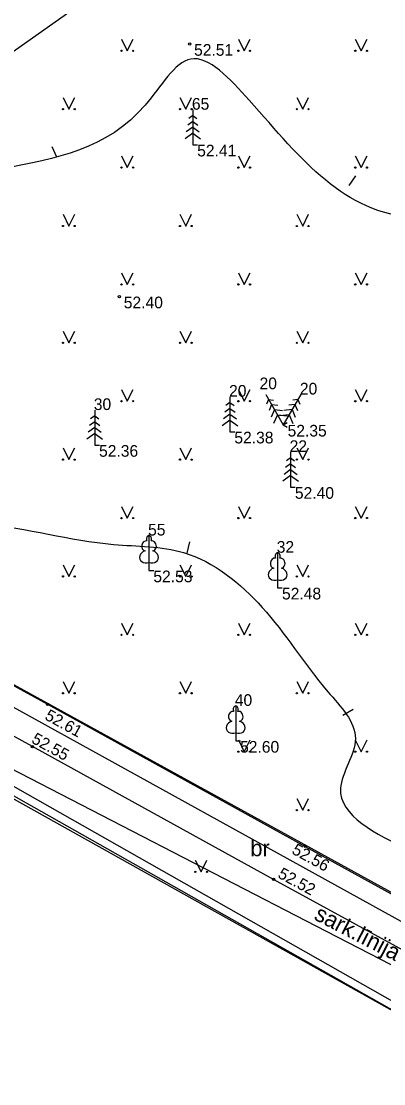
# Model space of a CAD drawing. Extents: x 619806 to 620082, y 405176 to 405386.
# Drawn here: x 619952.97 to 619968.46, y 405203.29 to 405248.76 of the extents above; entities that cross this region are included whole.
import ezdxf

# ---------------------------------------------------------------- set-up
doc = ezdxf.new("R2010")
doc.units = 0
for name, color, linetype in [('APGR_SARK_####_####_#', 7, 'Continuous'), ('APGR_SARK_IZNL_TKST_#', 7, 'Continuous'), ('APGS_VADP_ZSPR_####_#', 7, 'Continuous'), ('CELI_CMAL_####_####_#', 7, 'Continuous'), ('CELI_CSEG_####_TKST_#', 7, 'Continuous'), ('RAMI_UZMR_####_####_#', 7, 'Continuous'), ('RELJ_AATZ_####_TKST_#', 7, 'Continuous'), ('RELJ_ELEM_####_####_#', 7, 'Continuous'), ('RELJ_HORZ_PAMT_####_#', 7, 'Continuous'), ('ROBZ_UZMR_####_####_#', 7, 'Continuous'), ('SAKK_KKAN_####_####_#', 7, 'Continuous'), ('SAKT_VADP_KABE_####_#', 7, 'Continuous'), ('TERT_DIAM_####_TKST_#', 7, 'Continuous'), ('TERT_ELEM_####_####_#', 7, 'Continuous')]:
    doc.layers.add(name, color=color, linetype=linetype)

msp = doc.modelspace()

# ---------------------------------------------------------------- linework, layer by layer
at = {"layer": 'APGR_SARK_####_####_#'}
msp.add_lwpolyline([(619990.053, 405197.403), (619966.019, 405209.806), (619941.986, 405222.21), (619880.273, 405256.839), (619818.56, 405291.467)], dxfattribs=at)
at = {"layer": 'APGS_VADP_ZSPR_####_#'}
msp.add_lwpolyline([(619827.279, 405290.766), (619828.233, 405290.484), (619831.689, 405284.666), (619835.137, 405280.637), (619844.802, 405275.519), (619857.367, 405269.037), (619864.044, 405264.897), (619871.373, 405258.791), (619881.17, 405253.384), (619884.232, 405252.778), (619898.622, 405244.594), (619910.805, 405239.254), (619917.273, 405236.249), (619923.426, 405231.863), (619936.8, 405224.512), (619938.618, 405223.547), (619972.929, 405204.127)], dxfattribs=at)
at = {"layer": 'CELI_CMAL_####_####_#'}
for points in [[(619982.283, 405204.018), (619982.381, 405205.526), (619981.404, 405213.543), (619980.879, 405217.395), (619980.193, 405224.262), (619979.707, 405227.554), (619978.646, 405227.479), (619978.06, 405232.469), (619979.052, 405232.579), (619978.008, 405242.924), (619976.591, 405255.672), (619975.781, 405263.512), (619969.844, 405259.482), (619963.066, 405254.752), (619955.624, 405249.587), (619947.422, 405243.791), (619942.081, 405239.98), (619941.835, 405240.299), (619936.133, 405229.455), (619943.441, 405225.387), (619954.092, 405219.528), (619965.106, 405213.442), (619974.994, 405207.99), (619982.283, 405204.018)], [(619978.752, 405201.011), (619979.424, 405202.021), (619979.564, 405202.436), (619979.607, 405202.714), (619979.55, 405203.052), (619979.303, 405203.399), (619978.982, 405203.652), (619974.243, 405206.289), (619963.757, 405212.03), (619953.443, 405217.716), (619942.194, 405223.883), (619933.774, 405228.562), (619924.371, 405233.711), (619924.04, 405233.797), (619923.689, 405233.804), (619923.346, 405233.679), (619923.051, 405233.473), (619922.837, 405233.256), (619922.669, 405233.014)]]:
    msp.add_lwpolyline(points, dxfattribs=at)
at = {"layer": 'RAMI_UZMR_####_####_#'}
msp.add_lwpolyline([(619874.687, 405324.979), (619926.719, 405349.544), (619966.669, 405369.042), (620021.738, 405292.03), (620049.703, 405275.476), (620026.189, 405242.287), (620012.147, 405222.917), (619996.603, 405200.928), (619989.997, 405199.173), (619982.328, 405199.155), (619922.669, 405233.014), (619882.137, 405255.756), (619859.084, 405268.056), (619820.646, 405290.715), (619813.744, 405295.206), (619820.645, 405298.752)], close=True, dxfattribs=at)
at = {"layer": 'RELJ_ELEM_####_####_#'}
for centre in [(619960.169, 405247.788), (619957.163, 405236.978), (619954.092, 405219.528), (619953.443, 405217.716), (619965.106, 405213.442), (619963.757, 405212.03)]:
    msp.add_circle(centre, 0.05, dxfattribs=at)
at = {"layer": 'RELJ_HORZ_PAMT_####_#'}
for p, q in [((619954.489, 405242.94), (619954.285, 405243.396)), ((619966.986, 405241.735), (619967.276, 405242.143)), ((619960.16, 405226.477), (619960.046, 405225.991)), ((619967.156, 405219.304), (619966.723, 405219.054))]:
    msp.add_line(p, q, dxfattribs=at)
msp.add_spline([(619952.192, 405242.46), (619958.269, 405245.178), (619960.212, 405247.147), (619962.71, 405245.388), (619969.834, 405240.326), (619973.191, 405239.787), (619973.537, 405236.062), (619972.621, 405231.011), (619971.007, 405227.497), (619970.308, 405225.195), (619972.877, 405224.18), (619975.834, 405223.443), (619975.125, 405220.25), (619977.669, 405218.792), (619978.775, 405216.928), (619978.459, 405213.841), (619976.501, 405213.003), (619972.992, 405212.359), (619969.535, 405213.328), (619966.616, 405215.931), (619967.251, 405218.057), (619966.078, 405220.067), (619963.269, 405223.678), (619959.906, 405226.02), (619956.916, 405226.372), (619951.315, 405227.272), (619948.301, 405227.78), (619946.134, 405229.326), (619943.292, 405232.49), (619942.821, 405234.331), (619944.296, 405235.783), (619946.209, 405238.021), (619948.046, 405239.888), (619950.691, 405241.967), (619952.192, 405242.46)], degree=3, dxfattribs=at)
at = {"layer": 'ROBZ_UZMR_####_####_#'}
msp.add_line((619982.318, 405204.025), (619936.15, 405229.445), dxfattribs=at)
at = {"layer": 'SAKK_KKAN_####_####_#'}
msp.add_line((619979.31, 405204.647), (619918.714, 405238.138), dxfattribs=at)
at = {"layer": 'SAKT_VADP_KABE_####_#'}
msp.add_lwpolyline([(619817.668, 405301.762), (619818.308, 405291.251), (619820.058, 405288.244), (619821.78, 405286.435), (619865.996, 405262.382), (619894.538, 405246.913), (619928.954, 405228.717), (619988.18, 405195.595)], dxfattribs=at)
at = {"layer": 'TERT_ELEM_####_####_#'}
for p, q in [((619957.25, 405248), (619957.5, 405247.5)), ((619957.5, 405247.5), (619957.75, 405248)), ((619962.25, 405248), (619962.5, 405247.5)), ((619962.5, 405247.5), (619962.75, 405248)), ((619967.25, 405248), (619967.5, 405247.5)), ((619967.5, 405247.5), (619967.75, 405248)), ((619954.75, 405245.5), (619955, 405245)), ((619955, 405245), (619955.25, 405245.5)), ((619959.75, 405245.5), (619960, 405245)), ((619960, 405245), (619960.25, 405245.5)), ((619964.75, 405245.5), (619965, 405245)), ((619965, 405245), (619965.25, 405245.5)), ((619960.301, 405244.728), (619960.125, 405244.6)), ((619960.301, 405244.978), (619960.301, 405243.478)), ((619960.301, 405244.728), (619960.475, 405244.6)), ((619960.301, 405244.228), (619960.023, 405244.024)), ((619960.301, 405244.478), (619960.085, 405244.32)), ((619960.301, 405244.478), (619960.517, 405244.32)), ((619960.301, 405244.228), (619960.579, 405244.024)), ((619960.301, 405243.978), (619959.969, 405243.734)), ((619960.301, 405243.978), (619960.635, 405243.734)), ((619960.301, 405243.478), (619960.501, 405243.478)), ((619957.25, 405243), (619957.5, 405242.5)), ((619957.5, 405242.5), (619957.75, 405243)), ((619962.25, 405243), (619962.5, 405242.5)), ((619962.5, 405242.5), (619962.75, 405243)), ((619967.25, 405243), (619967.5, 405242.5)), ((619967.5, 405242.5), (619967.75, 405243)), ((619954.75, 405240.5), (619955, 405240)), ((619955, 405240), (619955.25, 405240.5)), ((619959.75, 405240.5), (619960, 405240)), ((619960, 405240), (619960.25, 405240.5)), ((619964.75, 405240.5), (619965, 405240)), ((619965, 405240), (619965.25, 405240.5)), ((619957.25, 405238), (619957.5, 405237.5)), ((619957.5, 405237.5), (619957.75, 405238)), ((619962.25, 405238), (619962.5, 405237.5)), ((619962.5, 405237.5), (619962.75, 405238)), ((619967.25, 405238), (619967.5, 405237.5)), ((619967.5, 405237.5), (619967.75, 405238)), ((619954.75, 405235.5), (619955, 405235)), ((619955, 405235), (619955.25, 405235.5)), ((619959.75, 405235.5), (619960, 405235)), ((619960, 405235), (619960.25, 405235.5)), ((619964.75, 405235.5), (619965, 405235)), ((619965, 405235), (619965.25, 405235.5)), ((619957.25, 405233), (619957.5, 405232.5)), ((619957.5, 405232.5), (619957.75, 405233)), ((619962.25, 405233), (619962.5, 405232.5)), ((619962.5, 405232.5), (619962.75, 405233)), ((619963.418, 405232.788), (619964.168, 405231.489)), ((619964.918, 405232.788), (619964.168, 405231.489)), ((619967.25, 405233), (619967.5, 405232.5)), ((619967.5, 405232.5), (619967.75, 405233)), ((619961.891, 405232.444), (619961.715, 405232.316)), ((619961.891, 405232.694), (619961.891, 405231.194)), ((619961.891, 405232.444), (619962.065, 405232.316)), ((619963.543, 405232.572), (619963.455, 405232.373)), ((619963.543, 405232.572), (619963.758, 405232.548)), ((619963.668, 405232.355), (619963.56, 405232.11)), ((619963.668, 405232.355), (619963.934, 405232.326)), ((619964.668, 405232.355), (619964.402, 405232.326)), ((619964.793, 405232.572), (619964.577, 405232.549)), ((619964.668, 405232.355), (619964.776, 405232.11)), ((619964.793, 405232.572), (619964.88, 405232.374)), ((619956.106, 405231.874), (619955.93, 405231.746)), ((619956.106, 405232.124), (619956.106, 405230.624)), ((619956.106, 405231.874), (619956.28, 405231.746)), ((619961.891, 405231.944), (619961.613, 405231.74)), ((619961.891, 405232.194), (619961.675, 405232.036)), ((619961.891, 405232.194), (619962.107, 405232.036)), ((619961.891, 405231.944), (619962.169, 405231.74)), ((619963.793, 405232.139), (619963.654, 405231.823)), ((619963.918, 405231.922), (619963.752, 405231.545)), ((619963.793, 405232.139), (619964.136, 405232.101)), ((619963.918, 405231.922), (619964.329, 405231.878)), ((619964.418, 405231.922), (619964.008, 405231.877)), ((619964.543, 405232.139), (619964.2, 405232.101)), ((619964.418, 405231.922), (619964.585, 405231.544)), ((619964.543, 405232.139), (619964.682, 405231.823)), ((619956.106, 405231.374), (619955.828, 405231.17)), ((619956.106, 405231.624), (619955.89, 405231.466)), ((619956.106, 405231.624), (619956.322, 405231.466)), ((619956.106, 405231.374), (619956.384, 405231.17)), ((619961.891, 405231.694), (619961.559, 405231.45)), ((619961.891, 405231.694), (619962.225, 405231.45)), ((619964.168, 405231.489), (619964.341, 405231.589)), ((619964.168, 405231.489), (619964.341, 405231.389)), ((619956.106, 405231.124), (619955.774, 405230.88)), ((619956.106, 405231.124), (619956.44, 405230.88)), ((619961.891, 405231.194), (619962.091, 405231.194)), ((619954.75, 405230.5), (619955, 405230)), ((619955, 405230), (619955.25, 405230.5)), ((619956.106, 405230.624), (619956.306, 405230.624)), ((619959.75, 405230.5), (619960, 405230)), ((619960, 405230), (619960.25, 405230.5)), ((619964.75, 405230.5), (619965, 405230)), ((619965, 405230), (619965.25, 405230.5)), ((619964.48, 405230.075), (619964.304, 405229.947)), ((619964.48, 405230.325), (619964.48, 405228.825)), ((619964.48, 405230.075), (619964.654, 405229.947)), ((619964.48, 405229.575), (619964.202, 405229.371)), ((619964.48, 405229.825), (619964.264, 405229.667)), ((619964.48, 405229.825), (619964.696, 405229.667)), ((619964.48, 405229.575), (619964.758, 405229.371)), ((619964.48, 405229.325), (619964.148, 405229.081)), ((619964.48, 405229.325), (619964.814, 405229.081)), ((619964.48, 405228.825), (619964.68, 405228.825)), ((619957.25, 405228), (619957.5, 405227.5)), ((619957.5, 405227.5), (619957.75, 405228)), ((619962.25, 405228), (619962.5, 405227.5)), ((619962.5, 405227.5), (619962.75, 405228)), ((619967.25, 405228), (619967.5, 405227.5)), ((619967.5, 405227.5), (619967.75, 405228)), ((619954.75, 405225.5), (619955, 405225)), ((619955, 405225), (619955.25, 405225.5)), ((619958.427, 405225.599), (619958.427, 405225.252)), ((619959.75, 405225.5), (619960, 405225)), ((619960, 405225), (619960.25, 405225.5)), ((619964.75, 405225.5), (619965, 405225)), ((619965, 405225), (619965.25, 405225.5)), ((619958.427, 405225.252), (619958.627, 405225.252)), ((619963.929, 405224.862), (619963.929, 405224.515)), ((619963.929, 405224.515), (619964.129, 405224.515)), ((619957.25, 405223), (619957.5, 405222.5)), ((619957.5, 405222.5), (619957.75, 405223)), ((619962.25, 405223), (619962.5, 405222.5)), ((619962.5, 405222.5), (619962.75, 405223)), ((619967.25, 405223), (619967.5, 405222.5)), ((619967.5, 405222.5), (619967.75, 405223)), ((619954.75, 405220.5), (619955, 405220)), ((619955, 405220), (619955.25, 405220.5)), ((619959.75, 405220.5), (619960, 405220)), ((619960, 405220), (619960.25, 405220.5)), ((619964.75, 405220.5), (619965, 405220)), ((619965, 405220), (619965.25, 405220.5)), ((619962.136, 405218.305), (619962.136, 405217.958)), ((619962.136, 405217.958), (619962.336, 405217.958)), ((619962.25, 405218), (619962.5, 405217.5)), ((619962.5, 405217.5), (619962.75, 405218)), ((619967.25, 405218), (619967.5, 405217.5)), ((619967.5, 405217.5), (619967.75, 405218)), ((619964.75, 405215.5), (619965, 405215)), ((619965, 405215), (619965.25, 405215.5)), ((619960.404, 405212.856), (619960.654, 405212.356)), ((619960.654, 405212.356), (619960.904, 405212.856))]:
    msp.add_line(p, q, dxfattribs=at)
for points in [[(619958.427, 405226.752), (619958.427, 405225.599)], [(619958.517, 405226.52), (619958.516, 405226.521)], [(619963.929, 405226.015), (619963.929, 405224.862)], [(619964.019, 405225.783), (619964.018, 405225.784)], [(619962.136, 405219.458), (619962.136, 405218.305)], [(619962.226, 405219.226), (619962.225, 405219.227)]]:
    msp.add_lwpolyline(points, dxfattribs=at)
for centre, radius in [((619957.25, 405247.5), 0.028), ((619957.75, 405247.5), 0.0263), ((619962.25, 405247.5), 0.028), ((619962.75, 405247.5), 0.0263), ((619967.25, 405247.5), 0.028), ((619967.75, 405247.5), 0.0263), ((619954.75, 405245), 0.028), ((619955.25, 405245), 0.0263), ((619959.75, 405245), 0.028), ((619960.25, 405245), 0.0263), ((619964.75, 405245), 0.028), ((619965.25, 405245), 0.0263), ((619957.25, 405242.5), 0.028), ((619957.75, 405242.5), 0.0263), ((619962.25, 405242.5), 0.028), ((619962.75, 405242.5), 0.0263), ((619967.25, 405242.5), 0.028), ((619967.75, 405242.5), 0.0263), ((619954.75, 405240), 0.028), ((619955.25, 405240), 0.0263), ((619959.75, 405240), 0.028), ((619960.25, 405240), 0.0263), ((619964.75, 405240), 0.028), ((619965.25, 405240), 0.0263), ((619957.25, 405237.5), 0.028), ((619957.75, 405237.5), 0.0263), ((619962.25, 405237.5), 0.028), ((619962.75, 405237.5), 0.0263), ((619967.25, 405237.5), 0.028), ((619967.75, 405237.5), 0.0263), ((619954.75, 405235), 0.028), ((619955.25, 405235), 0.0263), ((619959.75, 405235), 0.028), ((619960.25, 405235), 0.0263), ((619964.75, 405235), 0.028), ((619965.25, 405235), 0.0263), ((619957.25, 405232.5), 0.028), ((619957.75, 405232.5), 0.0263), ((619962.25, 405232.5), 0.028), ((619962.75, 405232.5), 0.0263), ((619967.25, 405232.5), 0.028), ((619967.75, 405232.5), 0.0263), ((619954.75, 405230), 0.028), ((619955.25, 405230), 0.0263), ((619959.75, 405230), 0.028), ((619960.25, 405230), 0.0263), ((619964.75, 405230), 0.028), ((619965.25, 405230), 0.0263), ((619957.25, 405227.5), 0.028), ((619957.75, 405227.5), 0.0263), ((619962.25, 405227.5), 0.028), ((619962.75, 405227.5), 0.0263), ((619967.25, 405227.5), 0.028), ((619967.75, 405227.5), 0.0263), ((619954.75, 405225), 0.028), ((619955.25, 405225), 0.0263), ((619959.75, 405225), 0.028), ((619960.25, 405225), 0.0263), ((619964.75, 405225), 0.028), ((619965.25, 405225), 0.0263), ((619957.25, 405222.5), 0.028), ((619957.75, 405222.5), 0.0263), ((619962.25, 405222.5), 0.028), ((619962.75, 405222.5), 0.0263), ((619967.25, 405222.5), 0.028), ((619967.75, 405222.5), 0.0263), ((619954.75, 405220), 0.028), ((619955.25, 405220), 0.0263), ((619959.75, 405220), 0.028), ((619960.25, 405220), 0.0263), ((619964.75, 405220), 0.028), ((619965.25, 405220), 0.0263), ((619962.25, 405217.5), 0.028), ((619962.75, 405217.5), 0.0263), ((619967.25, 405217.5), 0.028), ((619967.75, 405217.5), 0.0263), ((619964.75, 405215), 0.028), ((619965.25, 405215), 0.0263), ((619960.404, 405212.356), 0.028), ((619960.904, 405212.356), 0.0263)]:
    msp.add_circle(centre, radius, dxfattribs=at)
for centre, major_axis, ratio, start_param, end_param in [((619958.299, 405226.307), (-0.039, -0.212), 0.861323, 3.141593, 6.283185), ((619958.427, 405226.602), (0, -0.15), 0.707107, 3.14537, 5.287485), ((619958.427, 405226.602), (0, -0.15), 0.707107, 0.995701, 3.137816), ((619958.555, 405226.307), (0.039, -0.212), 0.861323, 0, 3.141593), ((619958.337, 405225.845), (0.307, 0.095), 0.814445, 1.570796, 4.752015), ((619958.517, 405225.845), (-0.307, 0.095), 0.814445, 1.531171, 4.712389), ((619963.929, 405225.865), (0, -0.15), 0.707107, 3.14537, 5.287485), ((619963.929, 405225.865), (0, -0.15), 0.707107, 0.995701, 3.137816), ((619963.801, 405225.57), (-0.039, -0.212), 0.861323, 3.141593, 6.283185), ((619964.057, 405225.57), (0.039, -0.212), 0.861323, 0, 3.141593), ((619963.839, 405225.108), (0.307, 0.095), 0.814445, 1.570796, 4.752015), ((619964.019, 405225.108), (-0.307, 0.095), 0.814445, 1.531171, 4.712389), ((619962.008, 405219.013), (-0.039, -0.212), 0.861323, 3.141593, 6.283185), ((619962.136, 405219.308), (0, -0.15), 0.707107, 3.14537, 5.287485), ((619962.136, 405219.308), (0, -0.15), 0.707107, 0.995701, 3.137816), ((619962.264, 405219.013), (0.039, -0.212), 0.861323, 0, 3.141593), ((619962.046, 405218.551), (0.307, 0.095), 0.814445, 1.570796, 4.752015), ((619962.226, 405218.551), (-0.307, 0.095), 0.814445, 1.531171, 4.712389)]:
    msp.add_ellipse(centre, major_axis=major_axis, ratio=ratio, start_param=start_param, end_param=end_param, dxfattribs=at)

# ---------------------------------------------------------------- texts
at = {"layer": 'APGR_SARK_IZNL_TKST_#'}
msp.add_text('sark.līnija', height=0.7, rotation=332.7019, dxfattribs=at).set_placement((619965.441, 405210.341))
at = {"layer": 'CELI_CSEG_####_TKST_#'}
msp.add_text('br', height=0.7, dxfattribs=at).set_placement((619962.761, 405213.024))
at = {"layer": 'RELJ_AATZ_####_TKST_#'}
for s, p in [(' 52.51', (619960.169, 405247.288)), (' 52.41', (619960.301, 405242.978)), (' 52.40', (619957.163, 405236.478)), (' 52.35', (619964.168, 405230.989)), (' 52.38', (619961.891, 405230.694)), (' 52.36', (619956.106, 405230.124)), (' 52.40', (619964.48, 405228.325)), (' 52.53', (619958.427, 405224.752)), (' 52.48', (619963.929, 405224.015)), (' 52.60', (619962.136, 405217.458))]:
    msp.add_text(s, height=0.5, dxfattribs=at).set_placement(p)
for s, rotation, p in [(' 52.61', 331.0763, (619953.769, 405218.995)), (' 52.55', 331.1325, (619953.202, 405217.993)), (' 52.56', 331.1287, (619964.336, 405213.249)), (' 52.52', 331.2997, (619963.736, 405212.222))]:
    msp.add_text(s, height=0.5, rotation=rotation, dxfattribs=at).set_placement(p)
at = {"layer": 'TERT_DIAM_####_TKST_#'}
for s, p in [(' 65', (619960.076, 405244.978)), (' 20', (619961.666, 405232.694)), (' 20', (619962.968, 405233.013)), (' 20', (619964.693, 405232.788)), (' 30', (619955.881, 405232.124)), (' 22', (619964.255, 405230.325)), (' 55', (619958.202, 405226.752)), (' 32', (619963.704, 405226.015)), (' 40', (619961.911, 405219.458))]:
    msp.add_text(s, height=0.5, dxfattribs=at).set_placement(p)

doc.saveas('drawing.dxf')
